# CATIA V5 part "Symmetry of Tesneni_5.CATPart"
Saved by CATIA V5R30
Part number: Symmetry of Tesneni_5
Bounding box of the stored display mesh (mm): x 0 to 1.2, y -6 to 6, z -6 to 6
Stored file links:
  E:\Bakalarka\Model\Forma_v7\Symmetry of Tesneni_5.CATPart
  E:\Bakalarka\Model\Forma_v7\Tesneni.CATPart
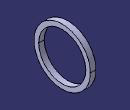
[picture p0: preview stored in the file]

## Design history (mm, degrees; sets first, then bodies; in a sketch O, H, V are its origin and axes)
Body1 (main body)
  Body2 "Body from original PartBody"
    Solid1: linked copy from another document
  Assemble1: tool Body2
